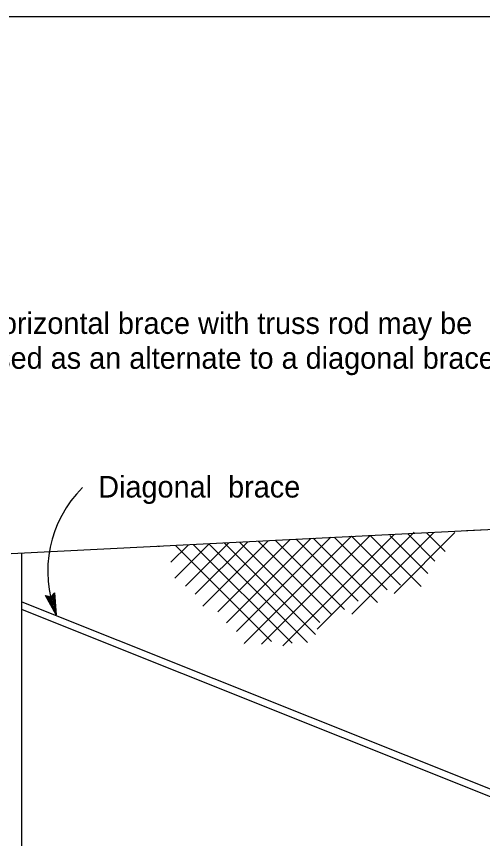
# Model space of a CAD drawing. Extents: x 6710407 to 6714861, y 1868090 to 1871317.
# Drawn here: x 6711708.8 to 6711838.5, y 1870376.3 to 1870605.1 of the extents above; entities that cross this region are included whole.
import ezdxf

# ---------------------------------------------------------------- set-up
doc = ezdxf.new("R2010")
doc.units = 0
for name, color, linetype in [('G-MARK', 7, 'Continuous'), ('G-TEXT', 7, 'Continuous'), ('G-TTLB-VIEW', 7, 'Continuous'), ('Nongeo Data(60)', 7, 'Continuous')]:
    doc.layers.add(name, color=color, linetype=linetype)

msp = doc.modelspace()

# ---------------------------------------------------------------- linework, layer by layer
at = {"layer": 'G-MARK'}
msp.add_arc((6711750.33, 1870450.77), 32.77, 134.9212, 201.8263, dxfattribs=at)
at = {"layer": 'G-TEXT'}
for p, q in [((6711718.41, 1870443.56), (6711719.46, 1870444.72)), ((6711719.46, 1870444.72), (6711719.46, 1870444.72)), ((6711719.46, 1870444.72), (6711719.91, 1870438.59)), ((6711719.91, 1870438.59), (6711716.91, 1870443.95)), ((6711716.91, 1870443.95), (6711716.91, 1870443.95)), ((6711716.91, 1870443.95), (6711718.41, 1870443.56)), ((6711719.51, 1870439.92), (6711717.32, 1870443.83)), ((6711719.12, 1870441.23), (6711717.7, 1870443.76)), ((6711718.72, 1870442.55), (6711718.11, 1870443.63)), ((6711718.63, 1870443.81), (6711718.72, 1870442.55)), ((6711718.91, 1870444.08), (6711719.12, 1870441.23)), ((6711719.18, 1870444.41), (6711719.51, 1870439.91)), ((6711719.91, 1870438.59), (6711719.91, 1870438.59))]:
    msp.add_line(p, q, dxfattribs=at)
at = {"layer": 'G-TTLB-VIEW'}
msp.add_lwpolyline([(6711433.78, 1870605.06), (6713227.53, 1870605.06), (6713227.53, 1869155.06), (6711433.78, 1869155.06)], close=True, dxfattribs=at)
at = {"layer": 'Nongeo Data(60)'}
for p, q in [((6711834, 1870462.01), (6711874.34, 1870464.05)), ((6711707.34, 1870455.62), (6711838.16, 1870462.22)), ((6711782.91, 1870429.94), (6711813.89, 1870460.93)), ((6711792.52, 1870434.57), (6711819.5, 1870461.55)), ((6711802.13, 1870438.72), (6711824.83, 1870461.42)), ((6711823.25, 1870450.11), (6711812.68, 1870460.69)), ((6711813.88, 1870444.54), (6711830.82, 1870461.48)), ((6711825.27, 1870453.55), (6711817.74, 1870461.08)), ((6711828.12, 1870456.16), (6711822.98, 1870461.3)), ((6711834, 1870462.01), (6711838.16, 1870462.22)), ((6711755.85, 1870446.55), (6711767.95, 1870458.65)), ((6711758.58, 1870444.3), (6711773.21, 1870458.93)), ((6711760.72, 1870440.98), (6711778.97, 1870459.23)), ((6711764.87, 1870439.43), (6711784.99, 1870459.55)), ((6711792.04, 1870433.14), (6711766.61, 1870458.58)), ((6711767.24, 1870436.35), (6711790.75, 1870459.85)), ((6711770.09, 1870433.97), (6711796.26, 1870460.15)), ((6711793.23, 1870436.47), (6711770.89, 1870458.81)), ((6711772.15, 1870430.58), (6711802.01, 1870460.44)), ((6711796.43, 1870438.72), (6711776.08, 1870459.08)), ((6711776.97, 1870430.41), (6711807.23, 1870460.67)), ((6711800.11, 1870440.03), (6711780.81, 1870459.33)), ((6711803.91, 1870442.4), (6711786.67, 1870459.64)), ((6711809.25, 1870442.04), (6711791.4, 1870459.89)), ((6711811.98, 1870445.49), (6711797.26, 1870460.2)), ((6711815.66, 1870446.79), (6711802.01, 1870460.44)), ((6711821.47, 1870446.43), (6711807.23, 1870460.67)), ((6711748.21, 1870457.68), (6711748.61, 1870457.7)), ((6711751.81, 1870453.2), (6711756.67, 1870458.05)), ((6711752.88, 1870448.81), (6711762.43, 1870458.36)), ((6711779.82, 1870431.13), (6711753.08, 1870457.86)), ((6711785.52, 1870430.65), (6711758.04, 1870458.13)), ((6711789.79, 1870430.89), (6711762.32, 1870458.35)), ((6711710.34, 1870355.53), (6711710.34, 1870455.77)), ((6711710.34, 1870442.2), (6711870.54, 1870378.19)), ((6711710.39, 1870440.02), (6711870.22, 1870376.14)), ((6711772.07, 1870430.32), (6711772.07, 1870430.32))]:
    msp.add_line(p, q, dxfattribs=at)

# ---------------------------------------------------------------- texts
for s, p in [('Horizontal brace with truss rod may be', (6711698.72, 1870516.73)), ('used as an alternate to a diagonal brace', (6711698.74, 1870507.04)), ('Diagonal  brace', (6711731.59, 1870471.21))]:
    msp.add_text(s, height=6, dxfattribs=at).set_placement(p)

doc.saveas('drawing.dxf')
